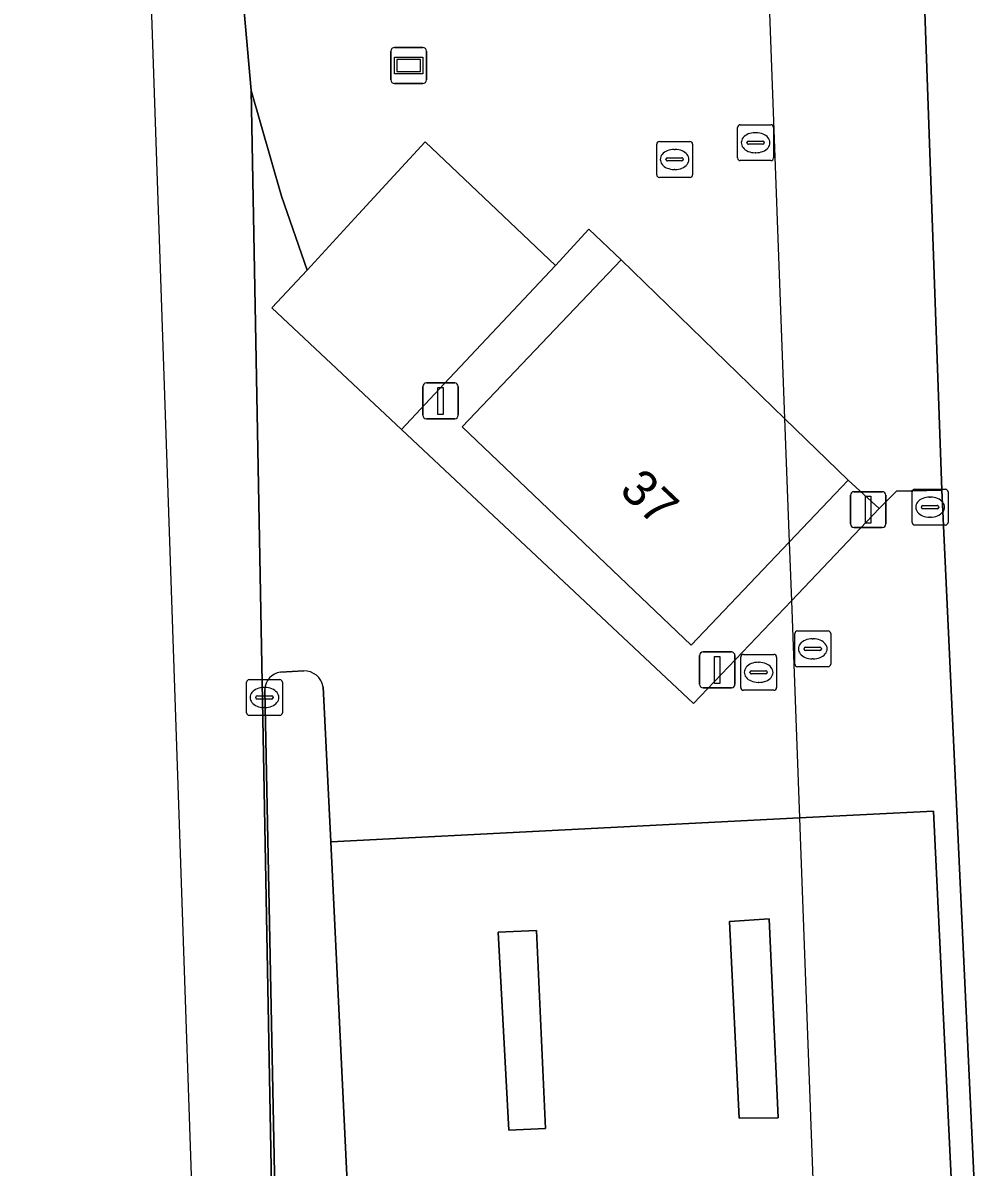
# Model space of a CAD drawing. Extents: x 162510 to 163918, y 388494 to 389774.
# Drawn here: x 162522.82 to 162549.5, y 388907.66 to 388939.56 of the extents above; entities that cross this region are included whole.
import ezdxf

# ---------------------------------------------------------------- set-up
doc = ezdxf.new("R2010")
doc.units = 0
for name, color, linetype in [('IMGEO_Berm_groen', 7, 'Continuous'), ('IMGEO_Duiker', 7, 'Continuous'), ('IMGEO_Kolk', 7, 'Continuous'), ('IMGEO_Lichtmast', 7, 'Continuous'), ('IMGEO_Muur', 7, 'Continuous'), ('IMGEO_Pand', 7, 'Continuous'), ('IMGEO_Pand_nummerreeks', 7, 'Continuous'), ('IMGEO_Parkeervlak_open', 7, 'Continuous'), ('IMGEO_Reclamebord', 7, 'Continuous'), ('IMGEO_Rijbaan_lokaal_gesloten', 7, 'Continuous'), ('IMGEO_Rijbaan_lokaal_open', 7, 'Continuous'), ('IMGEO_Rijbaan_regionaal_gesloten', 7, 'Continuous'), ('IMGEO_Rioolput', 7, 'Continuous'), ('IMGEO_Voetpad_open', 7, 'Continuous')]:
    doc.layers.add(name, color=color, linetype=linetype)

msp = doc.modelspace()

# ---------------------------------------------------------------- linework, layer by layer
at = {"layer": 'IMGEO_Berm_groen'}
msp.add_lwpolyline([(162528.084, 389000), (162528.341, 388968.251), (162528.689, 388944.843), (162528.839, 388941.677), (162529.193, 388937.678), (162530.043, 388934.731), (162530.757, 388932.669), (162532.187, 388934.223), (162534.049, 388936.247), (162537.685, 388932.796), (162538.613, 388933.806), (162539.511, 388932.95), (162544.076, 388928.528), (162545.846, 388926.813), (162546.717, 388926.017), (162547.197, 388926.503), (162548.457, 388926.534), (162547.973, 388940.397), (162544.704, 388940.345), (162543.637, 388940.341), (162542.875, 388940.338), (162540.824, 389000)], dxfattribs=at)
at = {"layer": 'IMGEO_Duiker'}
msp.add_lwpolyline([(162543.608, 388941.114), (162543.637, 388940.341), (162544.076, 388928.528), (162544.204, 388925.086), (162544.265, 388923.449), (162544.49, 388917.392), (162544.51, 388916.869), (162544.884, 388906.812), (162544.893, 388906.576), (162545.214, 388897.949), (162545.319, 388895.129), (162545.332, 388894.768)], dxfattribs=at)
at = {"layer": 'IMGEO_Kolk'}
for p, q in [((162547.709, 388926.558), (162548.561, 388926.558)), ((162547.634, 388925.632), (162547.634, 388926.484)), ((162548.122, 388926.338), (162548.147, 388926.338)), ((162548.635, 388926.484), (162548.635, 388925.632)), ((162547.893, 388926.052), (162547.893, 388926.064)), ((162548.331, 388926.015), (162547.933, 388926.015)), ((162547.936, 388926.101), (162548.334, 388926.101)), ((162548.377, 388926.064), (162548.377, 388926.052)), ((162548.145, 388925.778), (162548.12, 388925.778)), ((162548.561, 388925.558), (162547.709, 388925.558)), ((162542.85, 388921.026), (162542.85, 388921.878)), ((162542.925, 388921.952), (162543.777, 388921.952)), ((162543.851, 388921.878), (162543.851, 388921.026)), ((162543.109, 388921.446), (162543.109, 388921.458)), ((162543.152, 388921.495), (162543.55, 388921.495)), ((162543.338, 388921.732), (162543.363, 388921.732)), ((162543.593, 388921.458), (162543.593, 388921.446)), ((162529.064, 388920.324), (162529.064, 388921.176)), ((162529.139, 388921.25), (162529.991, 388921.25)), ((162530.065, 388921.176), (162530.065, 388920.324)), ((162543.547, 388921.409), (162543.149, 388921.409)), ((162543.361, 388921.172), (162543.336, 388921.172)), ((162529.552, 388921.03), (162529.577, 388921.03)), ((162543.777, 388920.952), (162542.925, 388920.952)), ((162529.323, 388920.744), (162529.323, 388920.756)), ((162529.761, 388920.707), (162529.363, 388920.707)), ((162529.366, 388920.793), (162529.764, 388920.793)), ((162529.807, 388920.756), (162529.807, 388920.744)), ((162529.991, 388920.25), (162529.139, 388920.25)), ((162529.575, 388920.47), (162529.55, 388920.47))]:
    msp.add_line(p, q, dxfattribs=at)
for points in [[(162547.709, 388926.558), (162548.561, 388926.558)], [(162547.634, 388925.632), (162547.634, 388926.484)], [(162548.635, 388926.484), (162548.635, 388925.632)], [(162548.561, 388925.558), (162547.709, 388925.558)], [(162542.85, 388921.026), (162542.85, 388921.878)], [(162542.925, 388921.952), (162543.777, 388921.952)], [(162543.851, 388921.878), (162543.851, 388921.026)], [(162529.064, 388920.324), (162529.064, 388921.176)], [(162529.139, 388921.25), (162529.991, 388921.25)], [(162530.065, 388921.176), (162530.065, 388920.324)], [(162543.777, 388920.952), (162542.925, 388920.952)], [(162529.991, 388920.25), (162529.139, 388920.25)]]:
    msp.add_lwpolyline(points, dxfattribs=at)
for centre, radius, start, end in [((162547.711, 388926.482), 0.0765, 91.552, 178.448), ((162547.711, 388926.482), 0.0765, 91.552, 178.448), ((162548.559, 388926.482), 0.0765, 1.552, 88.448), ((162548.559, 388926.482), 0.0765, 1.552, 88.448), ((162547.933, 388926.061), 0.0403, 85.8775, 175.7526), ((162547.93, 388926.051), 0.0366, 178.938, 274.7102), ((162548.334, 388926.058), 0.043, 264.8664, 352.4533), ((162548.338, 388926.063), 0.0386, 1.7309, 96.639), ((162547.711, 388925.634), 0.0765, 181.552, 268.448), ((162547.711, 388925.634), 0.0765, 181.552, 268.448), ((162548.559, 388925.634), 0.0765, 271.552, 358.448), ((162548.559, 388925.634), 0.0765, 271.552, 358.448), ((162542.927, 388921.876), 0.0765, 91.552, 178.448), ((162542.927, 388921.876), 0.0765, 91.552, 178.448), ((162543.775, 388921.876), 0.0765, 1.552, 88.448), ((162543.775, 388921.876), 0.0765, 1.552, 88.448), ((162543.149, 388921.455), 0.0403, 85.8775, 175.7526), ((162543.554, 388921.457), 0.0386, 1.7309, 96.639), ((162529.141, 388921.174), 0.0765, 91.552, 178.448), ((162529.141, 388921.174), 0.0765, 91.552, 178.448), ((162529.989, 388921.174), 0.0765, 1.552, 88.448), ((162529.989, 388921.174), 0.0765, 1.552, 88.448), ((162543.146, 388921.445), 0.0366, 178.938, 274.7102), ((162543.55, 388921.452), 0.043, 264.8664, 352.4533), ((162542.927, 388921.028), 0.0765, 181.552, 268.448), ((162542.927, 388921.028), 0.0765, 181.552, 268.448), ((162543.775, 388921.028), 0.0765, 271.552, 358.448), ((162543.775, 388921.028), 0.0765, 271.552, 358.448), ((162529.363, 388920.753), 0.0403, 85.8775, 175.7526), ((162529.36, 388920.743), 0.0366, 178.938, 274.7102), ((162529.764, 388920.75), 0.043, 264.8664, 352.4533), ((162529.768, 388920.755), 0.0386, 1.7309, 96.639), ((162529.141, 388920.326), 0.0765, 181.552, 268.448), ((162529.141, 388920.326), 0.0765, 181.552, 268.448), ((162529.989, 388920.326), 0.0765, 271.552, 358.448), ((162529.989, 388920.326), 0.0765, 271.552, 358.448)]:
    msp.add_arc(centre, radius, start, end, dxfattribs=at)
for centre, major_axis, ratio, start_param, end_param in [((162548.121, 388926.058), (-0.387, 0.002), 0.722429, 4.712389, 7.853982), ((162548.146, 388926.058), (-0.39, 0.002), 0.717154, 1.570796, 4.712389), ((162543.337, 388921.452), (-0.387, 0.002), 0.722429, 4.712389, 7.853982), ((162543.362, 388921.452), (-0.39, 0.002), 0.717154, 1.570796, 4.712389), ((162529.551, 388920.75), (-0.387, 0.002), 0.722429, 4.712389, 7.853982), ((162529.576, 388920.75), (-0.39, 0.002), 0.717154, 1.570796, 4.712389)]:
    msp.add_ellipse(centre, major_axis=major_axis, ratio=ratio, start_param=start_param, end_param=end_param, dxfattribs=at)
at = {"layer": 'IMGEO_Lichtmast'}
for p, q in [((162534.081, 388929.52), (162534.871, 388929.52)), ((162534.871, 388929.52), (162534.081, 388929.52)), ((162533.981, 388928.62), (162533.981, 388929.42)), ((162533.981, 388929.42), (162533.981, 388928.62)), ((162534.971, 388929.42), (162534.971, 388928.62)), ((162534.971, 388928.62), (162534.971, 388929.42)), ((162534.871, 388928.52), (162534.081, 388928.52)), ((162534.081, 388928.52), (162534.871, 388928.52)), ((162545.911, 388925.589), (162545.911, 388926.389)), ((162545.911, 388926.389), (162545.911, 388925.589)), ((162546.011, 388926.489), (162546.801, 388926.489)), ((162546.801, 388926.489), (162546.011, 388926.489)), ((162546.901, 388926.389), (162546.901, 388925.589)), ((162546.901, 388925.589), (162546.901, 388926.389)), ((162546.801, 388925.489), (162546.011, 388925.489)), ((162546.011, 388925.489), (162546.801, 388925.489)), ((162541.701, 388921.12), (162541.701, 388921.92)), ((162541.701, 388921.92), (162541.701, 388921.12)), ((162541.801, 388922.02), (162542.591, 388922.02)), ((162542.591, 388922.02), (162541.801, 388922.02)), ((162542.691, 388921.92), (162542.691, 388921.12)), ((162542.691, 388921.12), (162542.691, 388921.92)), ((162542.591, 388921.02), (162541.801, 388921.02)), ((162541.801, 388921.02), (162542.591, 388921.02))]:
    msp.add_line(p, q, dxfattribs=at)
for points in [[(162534.401, 388929.395), (162534.551, 388929.395), (162534.551, 388928.645), (162534.401, 388928.645), (162534.401, 388929.395)], [(162546.331, 388926.364), (162546.481, 388926.364), (162546.481, 388925.614), (162546.331, 388925.614), (162546.331, 388926.364)], [(162542.121, 388921.895), (162542.271, 388921.895), (162542.271, 388921.145), (162542.121, 388921.145), (162542.121, 388921.895)]]:
    msp.add_lwpolyline(points, dxfattribs=at)
for centre, start, end in [((162534.081, 388929.42), 90, 180), ((162534.081, 388929.42), 90, 180), ((162534.871, 388929.42), 0, 90), ((162534.871, 388929.42), 360, 90), ((162534.081, 388928.62), 180, 270), ((162534.081, 388928.62), 180, 270), ((162534.871, 388928.62), 270, 0), ((162534.871, 388928.62), 270, 0), ((162546.011, 388926.389), 90, 180), ((162546.011, 388926.389), 90, 180), ((162546.801, 388926.389), 0, 90), ((162546.801, 388926.389), 360, 90), ((162546.011, 388925.589), 180, 270), ((162546.011, 388925.589), 180, 270), ((162546.801, 388925.589), 270, 0), ((162546.801, 388925.589), 270, 0), ((162541.801, 388921.92), 90, 180), ((162541.801, 388921.92), 90, 180), ((162542.591, 388921.92), 0, 90), ((162542.591, 388921.92), 360, 90), ((162541.801, 388921.12), 180, 270), ((162541.801, 388921.12), 180, 270), ((162542.591, 388921.12), 270, 0), ((162542.591, 388921.12), 270, 0)]:
    msp.add_arc(centre, 0.1, start, end, dxfattribs=at)
at = {"layer": 'IMGEO_Muur'}
for points in [[(162543.898, 388909.031), (162543.64, 388914.581), (162542.537, 388914.506), (162542.807, 388909.02)], [(162537.408, 388908.733), (162537.152, 388914.255), (162536.087, 388914.209), (162536.38, 388908.687)]]:
    msp.add_lwpolyline(points, close=True, dxfattribs=at)
at = {"layer": 'IMGEO_Pand'}
msp.add_lwpolyline([(162539.511, 388932.95), (162535.084, 388928.294), (162541.469, 388922.21), (162544.204, 388925.086), (162545.846, 388926.813), (162544.076, 388928.528)], close=True, dxfattribs=at)
at = {"layer": 'IMGEO_Parkeervlak_open'}
msp.add_lwpolyline([(162530.757, 388932.669), (162529.768, 388931.618), (162533.388, 388928.227), (162534.577, 388929.497), (162537.685, 388932.796), (162534.049, 388936.247), (162532.187, 388934.223)], close=True, dxfattribs=at)
at = {"layer": 'IMGEO_Reclamebord'}
for p, q in [((162533.092, 388937.972), (162533.092, 388938.772)), ((162533.092, 388938.772), (162533.092, 388937.972)), ((162533.192, 388938.872), (162533.982, 388938.872)), ((162533.982, 388938.872), (162533.192, 388938.872)), ((162534.082, 388938.772), (162534.082, 388937.972)), ((162534.082, 388937.972), (162534.082, 388938.772)), ((162533.982, 388937.872), (162533.192, 388937.872)), ((162533.192, 388937.872), (162533.982, 388937.872))]:
    msp.add_line(p, q, dxfattribs=at)
for points in [[(162533.193, 388938.604), (162533.981, 388938.604), (162533.981, 388938.14), (162533.193, 388938.14), (162533.193, 388938.604)], [(162533.258, 388938.539), (162533.258, 388938.205), (162533.916, 388938.205), (162533.916, 388938.539), (162533.258, 388938.539)]]:
    msp.add_lwpolyline(points, dxfattribs=at)
for centre, start, end in [((162533.192, 388938.772), 90, 180), ((162533.192, 388938.772), 90, 180), ((162533.982, 388938.772), 0, 90), ((162533.982, 388938.772), 360, 90), ((162533.192, 388937.972), 180, 270), ((162533.192, 388937.972), 180, 270), ((162533.982, 388937.972), 270, 0), ((162533.982, 388937.972), 270, 0)]:
    msp.add_arc(centre, 0.1, start, end, dxfattribs=at)
at = {"layer": 'IMGEO_Rijbaan_lokaal_gesloten'}
for points in [[(162552.144, 389000), (162550.263, 389055.871), (162549.626, 389079.22), (162548.836, 389103.513), (162542.643, 389103.346), (162542.794, 389097.755), (162542.807, 389085.766), (162543.035, 389082.812), (162543.082, 389082.281), (162543.807, 389066.604), (162545.973, 389000), (162547.592, 388951.292), (162547.973, 388940.397), (162548.457, 388926.534), (162549.378, 388906.825), (162549.343, 388893.807), (162549.76, 388888.779), (162552.828, 388805.923), (162558.904, 388806.077), (162555.469, 388898.319), (162554.359, 388928.112)], [(162548.747, 388906.784), (162548.231, 388917.583), (162544.49, 388917.392), (162531.416, 388916.726), (162531.94, 388905.879), (162544.893, 388906.576)], [(162542.807, 388909.02), (162542.537, 388914.506), (162543.64, 388914.581), (162543.898, 388909.031)], [(162536.38, 388908.687), (162536.087, 388914.209), (162537.152, 388914.255), (162537.408, 388908.733)]]:
    msp.add_lwpolyline(points, close=True, dxfattribs=at)
at = {"layer": 'IMGEO_Rijbaan_lokaal_open'}
for points in [[(162544.743, 388898.421), (162545.214, 388897.949), (162549.343, 388893.807), (162549.378, 388906.825), (162548.457, 388926.534), (162547.197, 388926.503), (162546.717, 388926.017), (162544.265, 388923.449), (162541.53, 388920.585), (162533.388, 388928.227), (162529.768, 388931.618), (162530.757, 388932.669), (162530.043, 388934.731), (162529.193, 388937.678), (162530.485, 388868.12), (162533.787, 388868.298), (162534.385, 388875.971)], [(162530.009, 388921.456), (162530.659, 388921.497)], [(162530.124, 388893.52), (162529.574, 388920.976)], [(162531.202, 388921.043), (162531.416, 388916.726), (162544.49, 388917.392), (162548.231, 388917.583), (162548.747, 388906.784), (162544.893, 388906.576), (162531.94, 388905.879), (162531.678, 388893.59)]]:
    msp.add_lwpolyline(points, dxfattribs=at)
for centre, radius, start, end in [((162530.078, 388920.957), 0.504, 97.8158, 177.8153), ((162530.664, 388920.951), 0.546, 9.6812, 90.521)]:
    msp.add_arc(centre, radius, start, end, dxfattribs=at)
at = {"layer": 'IMGEO_Rijbaan_regionaal_gesloten'}
msp.add_lwpolyline([(162537.76, 388773.477), (162537.511, 388784.762), (162536.542, 388808.752), (162536.465, 388815.522), (162535.138, 388841.76), (162534.144, 388854.798), (162533.787, 388868.298), (162530.485, 388868.12), (162529.193, 388937.678), (162528.839, 388941.677), (162528.689, 388944.843), (162528.341, 388968.251), (162528.084, 389000), (162528.308, 389035.787), (162529.495, 389069.241), (162530.272, 389081.426), (162530.847, 389090.437), (162531.162, 389094.886), (162529.323, 389094.968), (162524.33, 389000.689), (162530.479, 388820.962), (162524.933, 388693.486), (162522.824, 388687.961)], dxfattribs=at)
at = {"layer": 'IMGEO_Rioolput'}
for p, q in [((162542.765, 388935.794), (162542.765, 388936.646)), ((162542.84, 388936.72), (162543.692, 388936.72)), ((162543.253, 388936.5), (162543.278, 388936.5)), ((162543.766, 388936.646), (162543.766, 388935.794)), ((162540.506, 388935.328), (162540.506, 388936.18)), ((162540.581, 388936.254), (162541.433, 388936.254)), ((162541.507, 388936.18), (162541.507, 388935.328)), ((162543.024, 388936.214), (162543.024, 388936.226)), ((162543.462, 388936.177), (162543.064, 388936.177)), ((162543.067, 388936.263), (162543.465, 388936.263)), ((162543.508, 388936.226), (162543.508, 388936.214)), ((162540.994, 388936.034), (162541.019, 388936.034)), ((162543.276, 388935.94), (162543.251, 388935.94)), ((162540.765, 388935.748), (162540.765, 388935.76)), ((162541.203, 388935.711), (162540.805, 388935.711)), ((162540.808, 388935.797), (162541.206, 388935.797)), ((162541.249, 388935.76), (162541.249, 388935.748)), ((162543.692, 388935.72), (162542.84, 388935.72)), ((162541.433, 388935.254), (162540.581, 388935.254)), ((162541.017, 388935.474), (162540.992, 388935.474)), ((162544.36, 388921.681), (162544.36, 388922.533)), ((162544.435, 388922.607), (162545.287, 388922.607)), ((162545.361, 388922.533), (162545.361, 388921.681)), ((162544.619, 388922.101), (162544.619, 388922.113)), ((162544.662, 388922.15), (162545.06, 388922.15)), ((162544.848, 388922.387), (162544.873, 388922.387)), ((162545.103, 388922.113), (162545.103, 388922.101)), ((162545.057, 388922.064), (162544.659, 388922.064)), ((162544.871, 388921.827), (162544.846, 388921.827)), ((162545.287, 388921.607), (162544.435, 388921.607))]:
    msp.add_line(p, q, dxfattribs=at)
for points in [[(162542.765, 388935.794), (162542.765, 388936.646)], [(162542.84, 388936.72), (162543.692, 388936.72)], [(162543.766, 388936.646), (162543.766, 388935.794)], [(162540.506, 388935.328), (162540.506, 388936.18)], [(162540.581, 388936.254), (162541.433, 388936.254)], [(162541.507, 388936.18), (162541.507, 388935.328)], [(162543.692, 388935.72), (162542.84, 388935.72)], [(162541.433, 388935.254), (162540.581, 388935.254)], [(162544.36, 388921.681), (162544.36, 388922.533)], [(162544.435, 388922.607), (162545.287, 388922.607)], [(162545.361, 388922.533), (162545.361, 388921.681)], [(162545.287, 388921.607), (162544.435, 388921.607)]]:
    msp.add_lwpolyline(points, dxfattribs=at)
for centre, radius, start, end in [((162542.842, 388936.644), 0.0765, 91.552, 178.448), ((162542.842, 388936.644), 0.0765, 91.552, 178.448), ((162543.69, 388936.644), 0.0765, 1.552, 88.448), ((162543.69, 388936.644), 0.0765, 1.552, 88.448), ((162540.583, 388936.178), 0.0765, 91.552, 178.448), ((162540.583, 388936.178), 0.0765, 91.552, 178.448), ((162541.431, 388936.178), 0.0765, 1.552, 88.448), ((162541.431, 388936.178), 0.0765, 1.552, 88.448), ((162543.064, 388936.223), 0.0403, 85.8775, 175.7526), ((162543.061, 388936.213), 0.0366, 178.938, 274.7102), ((162543.465, 388936.22), 0.043, 264.8664, 352.4533), ((162543.469, 388936.225), 0.0386, 1.7309, 96.639), ((162540.805, 388935.757), 0.0403, 85.8775, 175.7526), ((162540.802, 388935.747), 0.0366, 178.938, 274.7102), ((162541.206, 388935.754), 0.043, 264.8664, 352.4533), ((162541.21, 388935.759), 0.0386, 1.7309, 96.639), ((162542.842, 388935.796), 0.0765, 181.552, 268.448), ((162542.842, 388935.796), 0.0765, 181.552, 268.448), ((162543.69, 388935.796), 0.0765, 271.552, 358.448), ((162543.69, 388935.796), 0.0765, 271.552, 358.448), ((162540.583, 388935.33), 0.0765, 181.552, 268.448), ((162540.583, 388935.33), 0.0765, 181.552, 268.448), ((162541.431, 388935.33), 0.0765, 271.552, 358.448), ((162541.431, 388935.33), 0.0765, 271.552, 358.448), ((162544.437, 388922.531), 0.0765, 91.552, 178.448), ((162544.437, 388922.531), 0.0765, 91.552, 178.448), ((162545.285, 388922.531), 0.0765, 1.552, 88.448), ((162545.285, 388922.531), 0.0765, 1.552, 88.448), ((162544.659, 388922.11), 0.0403, 85.8775, 175.7526), ((162544.656, 388922.1), 0.0366, 178.938, 274.7102), ((162545.06, 388922.107), 0.043, 264.8664, 352.4533), ((162545.064, 388922.112), 0.0386, 1.7309, 96.639), ((162544.437, 388921.683), 0.0765, 181.552, 268.448), ((162544.437, 388921.683), 0.0765, 181.552, 268.448), ((162545.285, 388921.683), 0.0765, 271.552, 358.448), ((162545.285, 388921.683), 0.0765, 271.552, 358.448)]:
    msp.add_arc(centre, radius, start, end, dxfattribs=at)
for centre, major_axis, ratio, start_param, end_param in [((162543.252, 388936.22), (-0.387, 0.002), 0.722429, 4.712389, 7.853982), ((162543.277, 388936.22), (-0.39, 0.002), 0.717154, 1.570796, 4.712389), ((162540.993, 388935.754), (-0.387, 0.002), 0.722429, 4.712389, 7.853982), ((162541.018, 388935.754), (-0.39, 0.002), 0.717154, 1.570796, 4.712389), ((162544.847, 388922.107), (-0.387, 0.002), 0.722429, 4.712389, 7.853982), ((162544.872, 388922.107), (-0.39, 0.002), 0.717154, 1.570796, 4.712389)]:
    msp.add_ellipse(centre, major_axis=major_axis, ratio=ratio, start_param=start_param, end_param=end_param, dxfattribs=at)
at = {"layer": 'IMGEO_Voetpad_open'}
msp.add_lwpolyline([(162535.084, 388928.294), (162539.511, 388932.95), (162538.613, 388933.806), (162537.685, 388932.796), (162534.577, 388929.497), (162533.388, 388928.227), (162541.53, 388920.585), (162544.265, 388923.449), (162546.717, 388926.017), (162545.846, 388926.813), (162544.204, 388925.086), (162541.469, 388922.21)], close=True, dxfattribs=at)
for points in [[(162530.659, 388921.497), (162530.009, 388921.456)], [(162529.574, 388920.976), (162530.124, 388893.52)], [(162531.678, 388893.59), (162531.94, 388905.879), (162531.416, 388916.726), (162531.202, 388921.043)]]:
    msp.add_lwpolyline(points, dxfattribs=at)
for centre, radius, start, end in [((162530.078, 388920.957), 0.504, 97.8158, 177.8153), ((162530.664, 388920.951), 0.546, 9.6812, 90.521)]:
    msp.add_arc(centre, radius, start, end, dxfattribs=at)

# ---------------------------------------------------------------- texts
at = {"layer": 'IMGEO_Pand_nummerreeks'}
msp.add_text('37', height=1, rotation=316.473, dxfattribs=at).set_placement((162539.431, 388926.484))

doc.saveas('drawing.dxf')
